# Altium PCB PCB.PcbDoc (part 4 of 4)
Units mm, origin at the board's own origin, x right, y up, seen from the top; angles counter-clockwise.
Board outline 114 x 86.5 mm, 4 copper layers (TOP, GND, SIG, BOTTOM), stack 1.586 mm thick; 98 components, 195 nets, 719 pads, 522 vias.
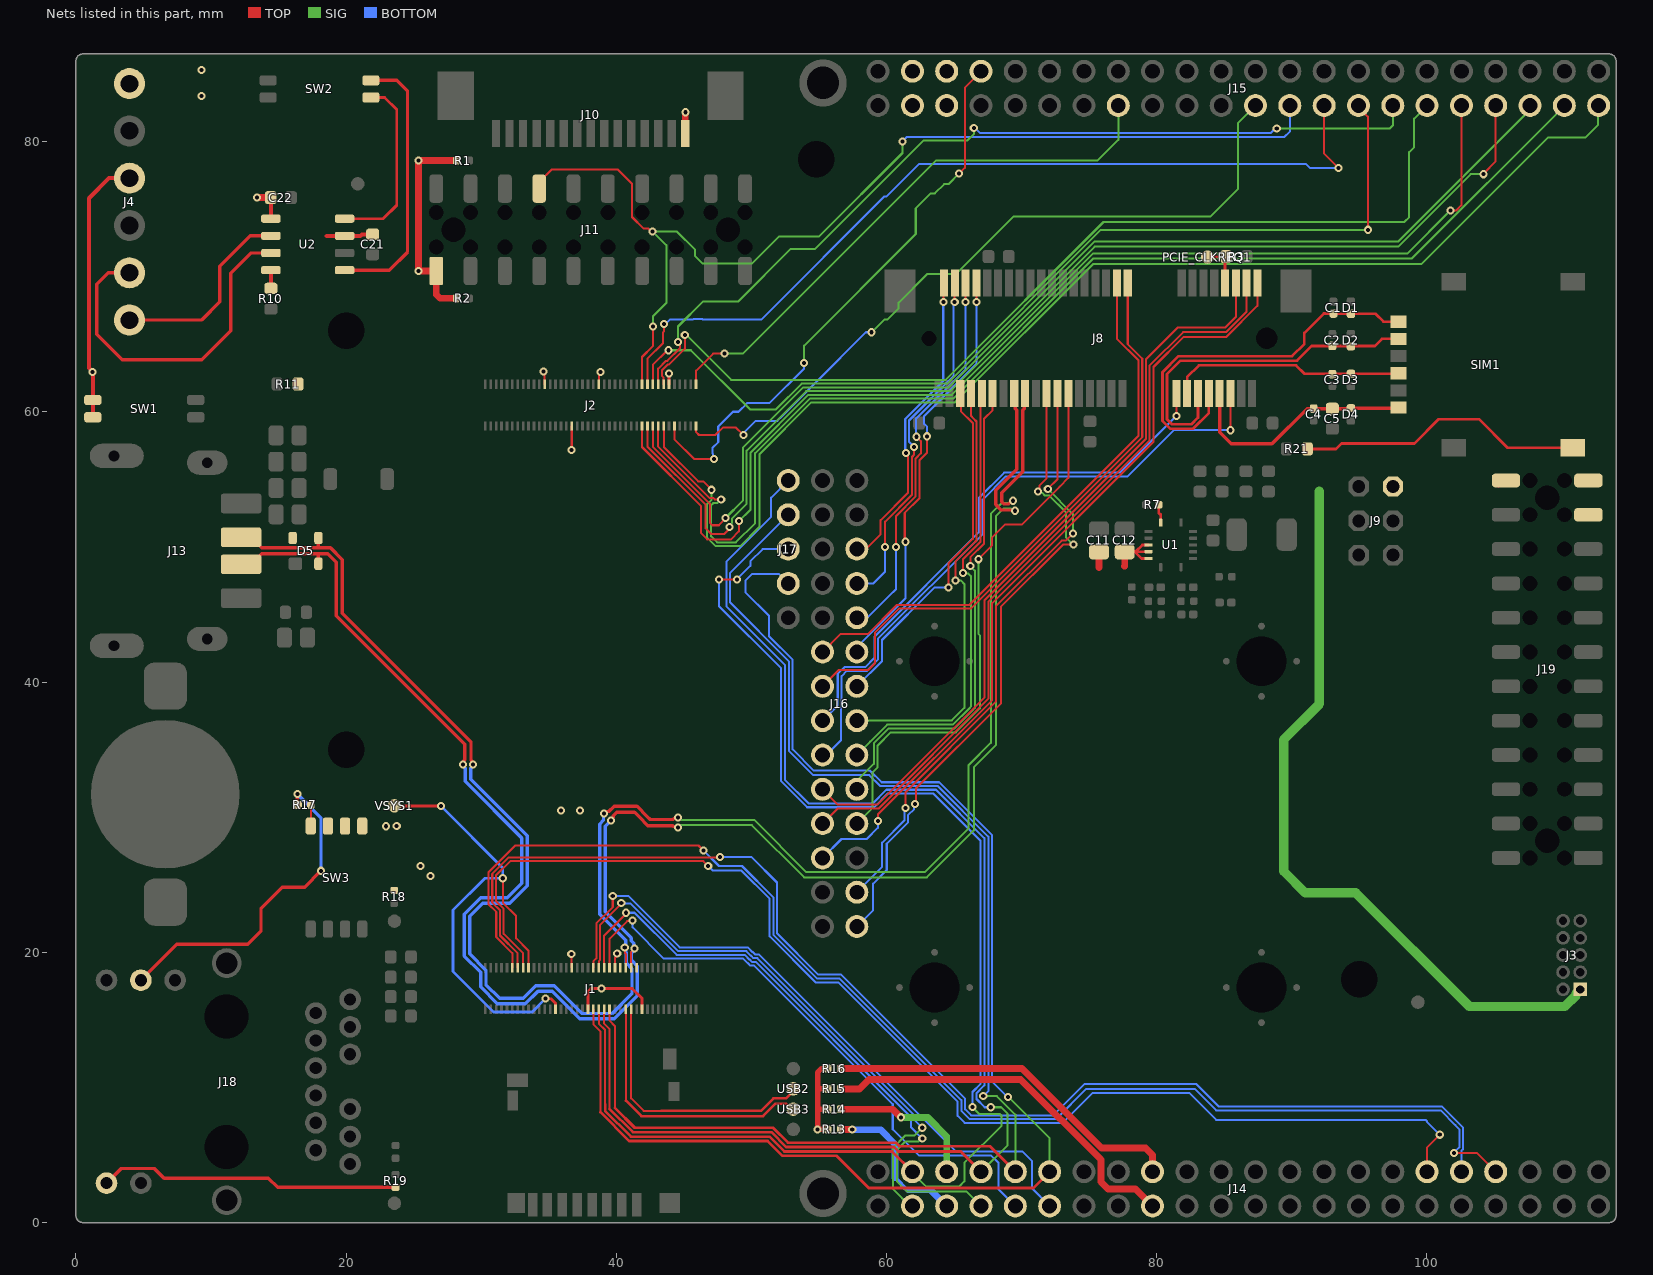
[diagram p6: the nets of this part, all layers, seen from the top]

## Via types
v1: diameter 0.6, hole 0.3, TOP to BOTTOM, tented both sides, 522 vias

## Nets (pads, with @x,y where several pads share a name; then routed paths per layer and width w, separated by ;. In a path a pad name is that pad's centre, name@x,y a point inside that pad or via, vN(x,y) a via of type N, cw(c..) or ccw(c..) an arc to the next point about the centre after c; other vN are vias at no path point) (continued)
NetJ2_79: J2.79 J15.15 | length 41.9
  TOP w0.15: J2.79@45.9,62.04 45.9,63.054 47.169,64.322 47.995,64.322 v1(48.001,64.316)
  SIG w0.15: v1(48.001,64.316) 49.37,64.316 63.672,78.619 75.633,78.619 77.154,80.14 J15.15@77.154,82.68
NetJ2_80: J2.80 J15.23 | length 55.7
  TOP w0.15: J2.80@45.9,58.96 45.9,58.51 46.117,58.293 47.33,58.293 47.881,58.844 48.856,58.844 v1(49.4,58.3)
  SIG w0.15: v1(58.9,65.9) 59.838,66.838 60.038,66.838 60.891,67.691 60.891,68.098 62.995,70.203 65.135,70.203 69.39,74.458 83.961,74.458 86.004,76.5 86.004,78.83 86.004,81.37 J15.23@87.314,82.68
  BOTTOM w0.15: v1(49.4,58.3) 49.4,58.42 50.325,59.345 51.911,59.345 52.261,59.695 54.74,62.174 58.466,65.9 v1(58.9,65.9)
NetJ4_5: J4.5 U2.7 | length 25.9
  TOP w0.25: J4.5@3.962,70.303 2.397,70.303 1.534,69.44 1.534,65.759 3.423,63.87 9.318,63.87 11.456,66.008 11.456,70.272 12.949,71.765 U2.7@14.432,71.765
NetJ4_6: J4.6 U2.6 | length 14.6
  TOP w0.25: J4.6@3.962,66.803 9.293,66.803 10.651,68.161 10.651,70.777 12.909,73.035 U2.6@14.432,73.035
NetJ8_7: J8.7 PCIE_CLKREQ1.X R3.2 | length 3.4
  TOP w0.2: PCIE_CLKREQ1.X@83.759,71.47 83.789,71.5 R3.2@85.125,71.5 85.056,71.431 J8.7@85.056,69.55
NetJ14_5: J14.5 R13.1 | length 11.7
  TOP w0.5: R13.1@56.593,6.892 56.602,6.884 57.454,6.884 v1(57.463,6.876)
  BOTTOM w0.3: 60.629,3.32 61.602,2.347 63.327,2.347
  BOTTOM w0.5: v1(57.463,6.876) 59.548,6.876 60.629,5.794 60.629,3.32 ; 63.327,2.347 J14.5@64.454,1.22
NetJ14_6: J14.6 R14.2 | length 11.3
  TOP w0.5: R14.2@56.593,8.392 60.454,8.392 v1(61.057,7.789)
  SIG w0.5: v1@61.081,7.765 61.086,7.77 61.147,7.77 61.152,7.765 63.074,7.765 64.454,6.385 J14.6@64.454,3.76
NetJ14_17: J14.17 R15.1 | length 28.2
  TOP w0.5: R15.1@56.593,9.892 57.993,9.892 58.693,10.592 69.932,10.592 75.874,4.651 75.874,3.014 76.403,2.485 78.429,2.485 J14.17@79.694,1.22
NetJ14_18: J14.18 R16.2 | length 27
  TOP w0.5: R16.2@56.593,11.392 70.035,11.392 75.918,5.51 79.181,5.51 79.694,4.997 J14.18@79.694,3.76
NetJ18_14: J18.14 R19.1 | length 22.4
  TOP w0.25: J18.14@2.262,2.915 3.347,4 5.8,4 6.517,3.283 14.242,3.283 14.921,2.604 R19.1@23.657,2.604
NetJ18_16: J18.16 R17.1 | length 24.9
  TOP w0.25: J18.16@4.802,17.935 7.467,20.6 12.704,20.6 13.7,21.596 13.7,23.256 15.268,24.824 16.924,24.824 v1(18.136,26.036) ; v1(16.39,31.721) 16.39,30.965 R17.1@16.445,30.91
  BOTTOM w0.25: v1(16.39,31.721) 18.136,29.975 v1(18.136,26.036)
NetR7_2: R7.2 U1.1 | length 1.4
  TOP w0.2: R7.2@80.149,53.127 80.148,52.541 80.299,52.39 U1.1@80.299,51.809
NetR10_2: R10.2 U2.8 | length 1.3
  TOP w0.3: R10.2@14.43,69.156 14.43,70.493 U2.8@14.432,70.495
NetR21_2: R21.2 SIM1.G3 | length 21.4
  TOP w0.2: R21.2@91.151,57.265 93.276,57.265 93.676,57.665 99.076,57.665 100.876,59.465 103.854,59.465 105.969,57.35 SIM1.G3@110.794,57.35
NetSW2_3: SW2.3 U2.4 | length 13.6
  TOP w0.2: U2.4@19.882,74.305 22.747,74.305 23.745,75.303 23.745,82.382 22.853,83.274 SW2.3@21.837,83.274
NetSW2_4: SW2.4 U2.1 | length 20.2
  TOP w0.25: U2.1@19.882,70.495 23.197,70.495 24.544,71.842 24.544,83.745 23.745,84.544 SW2.4@21.837,84.544
PDM.CK_1: J1.66 J14.34 | length 93.6
  TOP w0.15: J1.66@33.1,18.86 33.1,19.928 31.664,21.364 31.664,23.222 31.091,23.795 31.091,25.693 32.153,26.755 46.445,26.755 v1(46.8,26.4) ; J14.34@100.014,3.76 100.014,5.564 v1(100.95,6.5)
  BOTTOM w0.15: v1(46.8,26.4) 47.139,26.061 49.239,26.061 51.341,23.959 51.341,21.18 54.743,17.778 56.421,17.778 65.261,8.939 65.261,7.899 65.78,7.38 73.052,7.38 75.272,9.6 82.4,9.6 84.4,7.6 99.912,7.6 100,7.512 100,7.45 100.2,7.25 v1(100.95,6.5)
PDM.D0_1: J1.68 J14.36 | length 96.3
  TOP w0.15: J1.68@32.7,18.86 32.7,19.936 31.387,21.249 31.387,23.107 30.814,23.681 30.814,25.807 32.038,27.032 47.666,27.032 v1(47.684,27.049)
  BOTTOM w0.15: v1(47.684,27.049) 50.016,27.049 51.895,25.17 51.895,21.41 54.952,18.353 56.634,18.353 65.815,9.172 65.815,8.386 66.267,7.934 72.334,7.934 74.646,10.246 82.944,10.246 84.613,8.577 101.127,8.577 102.687,7.018 102.687,5.445 102.554,5.312 J14.36@102.554,3.76
PDM.D1_1: J1.70 J14.38 | length 98.7
  TOP w0.15: J1.70@32.3,18.86 32.3,19.944 31.11,21.134 31.11,22.992 30.537,23.566 30.537,25.922 32.522,27.907 46.083,27.907 v1(46.457,27.534) ; v1(102,5.15) 103.704,5.15 J14.38@105.094,3.76
  BOTTOM w0.15: v1(46.457,27.534) 47.6,26.39 49.301,26.39 51.618,24.074 51.618,21.295 54.858,18.055 56.536,18.055 65.538,9.053 65.538,8.271 66.152,7.657 72.547,7.657 74.79,9.9 82.8,9.9 84.4,8.3 101.013,8.3 102.108,7.204 102.41,6.903 102.41,5.56 v1(102,5.15)
PIN1_3: J8.1 J16.23 | length 58.8
  TOP w0.15: v1(59.357,29.732) 59.357,30.202 67.821,38.666 67.821,45.851 79.76,57.79 79.76,63.33 81.99,65.56 85.168,65.56 87.456,67.847 J8.1@87.456,69.55
  BOTTOM w0.15: J16.23@55.264,26.989 56.667,28.392 58.53,28.392 59.357,29.22 v1(59.357,29.732)
PIN3_3: J8.3 J16.21 | length 56.7
  TOP w0.15: J16.21@55.264,29.529 56.384,30.649 59.413,30.649 67.544,38.781 67.544,45.965 79.483,57.904 79.483,63.444 81.952,65.913 85.13,65.913 86.656,67.439 J8.3@86.656,69.55
PIN5_3: J8.5 J16.19 | length 56.2
  TOP w0.15: J16.19@55.264,32.069 56.4,30.933 59.305,30.933 67.267,38.896 67.267,46.08 79.206,58.019 79.206,63.906 81.549,66.249 85.074,66.249 85.856,67.031 J8.5@85.856,69.55
PIN6_3: J8.6 J16.17 | length 48
  TOP w0.15: v1@85.456,58.648 J8.6@85.456,61.35
  BOTTOM w0.15: J16.17@55.264,34.609 55.55,34.609 56.623,35.682 56.623,38.117 56.68,38.173 56.68,40.448 57.069,40.837 58.539,40.837 59.386,41.684 59.386,43.236 67.11,50.96 67.11,53.517 68.828,55.235 77.85,55.235 81.268,58.654 85.451,58.654 v1(85.458,58.647)
PIN16_3: J8.16 J16.15 | length 41
  TOP w0.15: v1(81.45,59.7) 81.45,61.344 J8.16@81.456,61.35
  BOTTOM w0.15: J16.15@55.264,37.149 56.389,38.274 56.389,40.616 56.887,41.114 58.424,41.114 59.109,41.799 59.109,43.357 66.833,51.081 66.833,53.632 68.713,55.512 77.262,55.512 v1(81.45,59.7)
PIN17_3: J8.17 J16.13 | length 44.5
  TOP w0.15: J16.13@55.264,39.689 56.476,40.901 58.66,40.901 59.141,41.383 59.141,43.658 60.919,45.436 65.417,45.436 66.231,45.436 78.929,58.134 78.929,58.877 78.929,63.951 77.856,65.024 J8.17@77.856,69.55
PIN19_3: J8.19 J16.11 | length 42
  TOP w0.15: J16.11@55.264,42.229 56.584,43.549 58.598,43.549 60.761,45.713 66.117,45.713 78.652,58.248 78.652,63.836 77.056,65.433 J8.19@77.056,69.55
PIN28_3: J8.28 J16.22 | length 41.9
  TOP w0.15: v1(66.8,49.1) 67.824,50.124 67.824,50.72 68.763,51.658 69.999,51.658 72.817,54.477 73.456,55.115 J8.28@73.456,61.35
  SIG w0.15: J16.22@57.804,29.529 58.945,30.671 58.945,33.294 59.342,33.69 59.342,35.31 60.322,36.29 65.139,36.29 66.91,38.061 66.91,43.464 66.823,43.551 66.823,49.077 v1(66.8,49.1)
PIN30_3: J8.30 J16.26 | length 44.8
  TOP w0.15: v1(61.403,30.687) 61.403,31.857 68.098,38.552 68.098,45.609 72.958,50.469 73.275,50.469 v1(73.798,50.992) ; v1(71.936,54.306) 72.656,55.025 J8.30@72.656,61.35
  SIG w0.15: v1(71.936,54.306) 73.798,52.444 v1(73.798,50.992)
  BOTTOM w0.15: J16.26@57.804,24.449 59.678,26.323 59.678,28.111 61.33,29.764 61.33,30.614 v1(61.403,30.687)
PIN32_3: J8.32 J16.28 | length 48.2
  TOP w0.15: v1(62.098,30.992) 62.184,31.078 62.184,32.136 68.464,38.415 68.464,45.583 73.073,50.192 v1(73.837,50.192) ; v1(71.205,54.099) 71.205,54.22 71.338,54.352 71.338,54.563 71.856,55.081 J8.32@71.856,61.35
  SIG w0.15: v1(71.205,54.099) 71.292,54.012 71.52,54.012 71.729,53.804 72.047,53.804 73.291,52.559 73.291,50.7 73.799,50.192 v1(73.837,50.192)
  BOTTOM w0.15: J16.28@57.804,21.909 59.013,23.118 59.013,25.089 60.016,26.092 60.016,28.046 61.607,29.637 61.607,30.173 62.041,30.607 62.041,30.935 v1(62.098,30.992)
PIN42_3: J8.42 J16.20 | length 36.6
  TOP w0.15: v1(66.2,48.6) 66.2,49.243 67.216,50.259 67.216,59.493 67.856,60.133 J8.42@67.856,61.35
  SIG w0.15: J16.20@57.804,32.069 57.804,32.689 59.064,33.949 59.064,35.485 60.162,36.583 65.032,36.583 66.38,37.931 66.546,38.097 66.546,48.254 v1(66.2,48.6)
PIN44_3: J8.44 J16.18 | length 34.1
  TOP w0.15: v1(65.663,48.071) 65.663,49.098 66.939,50.374 66.939,61.233 J8.44@67.056,61.35
  SIG w0.15: J16.18@57.804,34.609 58.787,35.592 58.787,35.6 60.047,36.86 60.055,36.86 60.072,36.877 64.934,36.877 66.103,38.046 66.269,38.212 66.269,47.82 66.063,48.026 65.708,48.026 v1(65.663,48.071)
PIN45_3: J8.45 J16.12 | length 31.2
  TOP w0.15: v1(61.398,50.392) 61.348,50.443 61.348,52.529 62.438,53.619 62.438,56.438 63,57 v1(63,58.2) ; J8.45@66.656,69.55 66.659,69.546 v1(66.659,68.14)
  BOTTOM w0.15: J16.12@57.804,42.229 57.804,42.598 61.398,46.192 v1(61.398,50.392) ; v1(63,58.2) 63,58.901 62.779,59.121 62.779,59.7 66.659,63.58 v1(66.659,68.14)
PIN46_3: J8.46 J16.16 | length 32.9
  TOP w0.15: v1(65.1,47.538) 65.1,48.926 66.431,50.257 66.662,50.488 66.662,59.297 66.431,59.529 66.256,59.703 J8.46@66.256,61.35
  SIG w0.15: J16.16@57.804,37.149 57.819,37.164 64.83,37.164 65.766,38.101 65.766,47.265 65.5,47.532 65.106,47.532 v1(65.1,47.538)
PIN47_3: J8.47 J16.10 | length 28.9
  TOP w0.15: v1(60.698,49.992) 60.698,52.284 62.161,53.747 62.161,56.553 62.537,56.929 62.537,57.841 v1(62.21,58.167) ; v1(65.857,68.153) J8.47@65.856,69.55
  BOTTOM w0.15: J16.10@57.804,44.769 58.584,44.769 60.2,46.386 60.698,46.884 v1(60.698,49.992) ; v1(62.21,58.167) 62.165,58.213 62.165,59.477 65.857,63.169 v1(65.857,68.153)
PIN48_3: J8.48 J16.14 | length 26.2
  TOP w0.15: v1(64.6,47) 64.6,47.328 64.598,47.33 64.598,47.746 64.6,47.748 64.6,48.818 66.385,50.603 66.385,59.182 65.5,60.068 65.5,61.306 J8.48@65.456,61.35
  BOTTOM w0.15: J16.14@57.804,39.689 59.663,41.548 59.663,43.121 63.542,47 v1(64.6,47)
PIN49_3: J8.49 J16.8 | length 26.3
  TOP w0.15: v1(59.898,49.992) 59.898,51.876 61.884,53.861 61.884,56.668 62.035,56.818 v1(62.035,57.411) ; v1(65.048,68.14) 65.048,69.542 J8.49@65.056,69.55
  BOTTOM w0.15: J16.8@57.804,47.309 59.035,47.309 59.887,48.161 59.887,49.981 v1(59.898,49.992) ; v1(62.035,57.411) 61.663,57.783 61.663,59.367 64.963,62.667 64.963,68.055 v1(65.048,68.14)
PIN51_3: J8.51 J16.6 | length 22.9
  TOP w0.15: J16.6@57.804,49.849 58.464,49.849 59.564,50.949 59.564,51.988 61.587,54.011 61.587,56.71 61.446,56.85 v1(61.446,56.972) ; v1(64.226,68.128) 64.226,69.52 J8.51@64.256,69.55
  BOTTOM w0.15: v1(61.446,56.972) 61.386,57.033 61.386,59.482 64.198,62.294 64.198,68.1 v1(64.226,68.128)
PWM0_1: J2.59 J11.8 J15.25 | length 80
  TOP w0.15: J11.8@34.29,76.535 34.29,77.031 35.204,77.945 40.096,77.945 41.158,76.883 41.158,74.433 42.028,73.563 42.374,73.563 42.584,73.354 v1(42.687,73.354) ; J2.59@41.9,62.04 41.9,64.068 42.7,64.868 42.7,66.327 v1(42.702,66.329)
  SIG w0.15: v1(42.702,66.329) 42.702,67.066 43.704,68.068 43.704,69.96 43.698,69.966 43.698,72.343 v1(42.687,73.354) 44.491,73.354 45.839,72.006 45.839,71.528 46.367,71 50.049,71 52.05,73.001 55.017,73.001 61.185,79.168 v1(61.185,80.033)
  BOTTOM w0.15: v1(61.185,80.033) 61.513,80.362 89.459,80.362 89.854,80.757 J15.25@89.854,82.68
PWM5: J2.60 J15.35 | length 86.8
  TOP w0.15: J2.60@41.9,58.96 41.9,57.405 46.271,53.034 46.271,51.023 46.719,50.575 48.496,50.575 49.076,51.156 v1(49.076,51.916) ; v1(101.735,74.916) 102.165,74.916 102.548,75.299 102.548,82.674 J15.35@102.554,82.68
  SIG w0.15: v1(49.076,51.916) 49.93,52.77 49.93,56.99 54.207,61.267 64.83,61.267 75.277,71.714 98.534,71.714 v1(101.735,74.916)
PWM6: J2.62 J15.37 | length 86.2
  TOP w0.15: J2.62@42.3,58.96 42.3,57.446 46.616,53.13 46.616,51.383 47.032,50.967 47.975,50.967 48.375,51.368 v1(48.375,51.473) ; v1(104.2,77.6) 104.2,77.651 105.094,78.545 J15.37@105.094,82.68
  SIG w0.15: v1(48.375,51.473) 48.375,51.594 48.574,51.793 48.574,52.124 49.646,53.196 49.646,57.136 54.054,61.544 64.715,61.544 75.405,72.234 97.874,72.234 103.241,77.6 v1(104.2,77.6)
PWM7: J2.64 J15.39 | length 85.1
  TOP w0.15: J2.64@42.7,58.96 42.7,57.438 46.926,53.212 46.926,51.789 47.102,51.614 47.592,51.614 48.073,52.095 v1(48.073,52.15)
  SIG w0.15: v1(48.073,52.15) 48.08,52.15 49.364,53.433 49.364,57.345 53.84,61.821 64.6,61.821 75.391,72.612 97.861,72.612 107.634,82.385 J15.39@107.634,82.68
PWM8: J2.66 J15.41 | length 90.8
  TOP w0.15: J2.66@43.1,58.96 43.1,57.429 46.892,53.637 47.162,53.637 47.274,53.526 v1(47.762,53.526)
  SIG w0.15: v1(47.762,53.526) 47.729,53.526 47.463,53.26 47.191,53.26 47.015,53.084 47.015,50.791 47.458,50.348 47.879,50.348 48.29,50.348 48.852,50.348 50.278,51.774 50.278,56.946 54.322,60.99 64.945,60.99 75.311,71.357 76.037,71.357 98.486,71.357 98.887,71.357 110.174,82.645 J15.41@110.174,82.68
PWM9: J2.68 J15.43 | length 93.8
  TOP w0.15: J2.68@43.5,58.96 43.512,58.948 43.512,57.409 46.051,54.87 46.397,54.87 46.425,54.87 v1(47.056,54.239)
  SIG w0.15: v1(47.056,54.239) 47.056,53.517 46.724,53.185 46.724,50.691 47.343,50.071 48.405,50.071 49.181,50.071 50.598,51.488 50.598,56.875 54.437,60.713 65.059,60.713 75.283,70.937 99.287,70.937 99.586,70.937 108.95,80.301 111.718,80.301 112.65,81.233 112.65,82.616 J15.43@112.714,82.68
PWM.1_1: J2.61 J15.27 | length 65.1
  TOP w0.15: J2.61@42.3,62.04 42.3,63.945 43.452,65.097 43.452,65.887 43.544,65.978 43.544,66.487 v1(43.519,66.512) ; J15.27@92.394,82.68 92.394,79.115 v1(93.464,78.045)
  BOTTOM w0.15: v1(43.519,66.512) 43.634,66.512 43.977,66.855 45.682,66.855 45.719,66.892 46.356,66.892 46.393,66.855 50.75,66.855 59.85,75.955 60.008,75.955 62.394,78.342 91.059,78.342 91.356,78.045 v1(93.464,78.045)
PWM.2_1: J2.63 J15.29 | length 71.6
  TOP w0.15: J2.63@42.7,62.04 42.7,63.48 43.79,64.569 v1(43.853,64.569) ; J15.29@94.934,82.68 94.934,82.565 95.635,81.865 v1(95.635,73.485)
  SIG w0.15: v1(43.853,64.569) 43.854,64.568 45.519,64.568 49.904,60.183 51.81,60.183 53.725,62.098 64.486,62.098 75.872,73.485 v1(95.635,73.485)
PWM.3_1: J2.65 J15.31 | length 66.2
  TOP w0.15: J2.65@43.1,62.04 43.1,63.211 43.675,63.785 43.78,63.785 44.728,64.733 44.728,64.885 44.564,65.048 v1(44.564,65.17)
  SIG w0.15: v1(44.564,65.17) 44.564,66.324 46.433,68.194 49.043,68.194 52.923,72.074 54.717,72.074 62.744,80.101 65.995,80.101 66.459,80.565 v1(66.459,81.013) ; v1(88.885,80.981) 97.248,80.981 97.474,81.206 J15.31@97.474,82.68
  BOTTOM w0.15: v1(66.459,81.013) 66.558,81.013 66.933,80.639 88.422,80.639 88.764,80.981 v1(88.885,80.981)
PWM.4_1: J2.67 J15.33 | length 73.3
  TOP w0.15: J2.67@43.5,62.04 43.5,62.533 43.386,62.647 43.386,63.104 43.79,63.508 43.895,63.508 45.066,64.68 v1(45.066,65.707)
  SIG w0.15: v1(45.066,65.707) 45.163,65.707 48.495,62.375 64.371,62.375 76.058,74.062 98.326,74.062 98.684,74.421 98.684,79.235 99.05,79.601 99.05,81.716 J15.33@100.014,82.68
SERIAL0.CTS_1: J1.40 J14.11 | length 49
  TOP w0.15: J1.40@38.3,18.86 38.3,19.325 38.527,19.552 38.527,22.144 39.735,23.352 v1(39.735,24.18)
  BOTTOM w0.15: v1(39.735,24.18) 40.878,24.18 44.695,20.363 49.737,20.363 50.075,20.024 50.09,20.024 50.263,19.851 50.545,19.851 65.149,5.247 70.074,5.247 70.774,4.547 70.774,2.52 J14.11@72.074,1.22
SERIAL0.RTS_1: J1.38 J14.3 | length 42.6
  TOP w0.15: J1.38@38.7,18.86 38.7,19.333 38.804,19.437 38.804,22.029 40.365,23.59 v1(40.365,23.659)
  SIG w0.15: J14.3@61.914,1.22 61.74,1.22 60.482,2.478 60.482,5.542 61.368,6.427 62.052,6.427 v1(62.643,7.017)
  BOTTOM w0.15: v1(40.365,23.659) 40.423,23.602 41.064,23.602 44.58,20.086 49.622,20.086 49.96,19.747 49.975,19.747 50.148,19.574 50.43,19.574 62.091,7.914 62.091,7.569 v1(62.643,7.017)
SERIAL0.RX_1: J1.36 J14.7 | length 45.6
  TOP w0.15: J1.36@39.1,18.86 39.1,19.989 39.099,19.99 39.099,21.247 40.727,22.875 v1(40.727,22.931)
  SIG w0.15: v1(62.647,6.206) 62.543,6.206 62.334,5.997 61.39,5.997 60.763,5.371 60.763,3.053 61.511,2.305 65.909,2.305 J14.7@66.994,1.22
  BOTTOM w0.15: v1(40.727,22.931) 41.343,22.931 44.465,19.809 49.507,19.809 49.846,19.47 49.86,19.47 50.033,19.297 50.316,19.297 61.814,7.799 61.814,7.04 v1(62.647,6.206)
SERIAL0.TX_1: J1.34 J14.9 | length 44
  TOP w0.15: J1.34@39.509,18.869 39.509,21.011 40.803,22.305 41.155,22.305 v1(41.2,22.35)
  BOTTOM w0.15: v1(41.2,22.35) 41.2,21.843 43.512,19.532 49.392,19.532 49.731,19.193 49.745,19.193 49.919,19.02 50.201,19.02 60.46,8.761 60.46,6.9 62.39,4.97 67.729,4.97 68.288,4.41 68.288,2.466 J14.9@69.534,1.22
SERIAL1.CTS_1: J1.39 J14.12 J17.4 | length 105.6
  TOP w0.15: J1.39@38.3,15.78 38.3,14.669 38.813,14.155 38.813,8.167
  TOP w0.2: 38.813,8.167 40.947,6.033 51.2,6.033 52.3,4.933 56.315,4.933 58.686,2.562 70.876,2.562 J14.12@72.074,3.76
  SIG w0.15: v1(69,9.3) 72.074,6.226 J14.12@72.074,3.76
  BOTTOM w0.15: J17.4@52.724,47.309 52.021,48.012 50.049,48.012 49.553,47.517 49.553,46.647 51.3,44.9 51.3,43.405 53.054,41.651 53.054,35.024 54.624,33.455 58.779,33.455 59.644,32.59 63.894,32.59 67.813,28.671 67.813,10.411 68.923,9.3 v1(69,9.3)
SERIAL1.RTS_1: J1.37 J14.4 J17.3 | length 105.7
  TOP w0.15: J1.37@38.7,15.78 38.7,14.726 39.173,14.253 39.173,8.732 ; v1(47.598,47.592) 47.606,47.599 48.915,47.599 v1(48.922,47.607)
  TOP w0.2: 39.173,8.732 39.173,8.27 41.083,6.36 51.336,6.36 52.436,5.26 60.414,5.26 J14.4@61.914,3.76
  SIG w0.15: J14.4@61.914,3.76 61.914,3.663 62.926,2.651 65.365,2.651 65.764,3.049 65.764,4.417 68.517,7.17 68.517,7.893 68.377,8.032 66.879,8.032 v1(66.366,8.545)
  BOTTOM w0.15: v1(47.598,47.592) 47.598,45.615 52.195,41.019 52.195,32.668 54.123,30.74 59.085,30.74 60.103,31.759 63.455,31.759 66.971,28.243 66.971,10.265 66.366,9.66 v1(66.366,8.545) ; v1(48.922,47.607) 49.918,48.603 49.918,48.939 50.828,49.849 J17.3@52.724,49.849
SERIAL1.RX_1: J1.35 J14.8 J17.1 | length 107.6
  TOP w0.15: J1.35@39.1,15.78 39.1,14.718 39.5,14.318 39.5,8.405
  TOP w0.2: 39.5,8.405 41.218,6.687 51.471,6.687 52.571,5.587 60.55,5.587 60.877,5.26 65.494,5.26 J14.8@66.994,3.76
  SIG w0.15: J14.8@66.994,3.76 68.964,5.73 68.964,8.049 68.479,8.534 v1(67.715,8.534)
  BOTTOM w0.15: J17.1@52.724,54.929 51.452,53.657 51.452,52.237 48.142,48.927 48.142,45.616 52.472,41.286 52.472,32.783 54.237,31.017 58.97,31.017 59.988,32.036 63.665,32.036 67.248,28.453 67.248,10.15 66.658,9.561 66.658,9.145 67.269,8.534 v1(67.715,8.534)
SERIAL1.TX_1: J1.33 J14.10 J17.2 | length 104
  TOP w0.15: J1.33@39.5,15.78 39.5,14.944 39.9,14.544 39.9,8.479
  TOP w0.2: 39.9,8.479 41.365,7.014 51.606,7.014 52.707,5.914 60.685,5.914 60.952,5.647 67.647,5.647 J14.10@69.534,3.76
  SIG w0.15: v1(67.16,9.353) 68.161,9.353 69.534,7.979 J14.10@69.534,3.76
  BOTTOM w0.15: J17.2@52.724,52.389 48.419,48.084 48.419,45.895 52.777,41.536 52.777,34.91 54.566,33.121 58.72,33.121 59.529,32.313 63.779,32.313 67.536,28.556 67.536,9.728 v1(67.16,9.353)
USB0_D_N: D5.3 J1.28 J8.36 J13.2 | length 145.2
  TOP w0.15: v1(40.624,20.373) 40.624,19.951 40.725,19.85 40.725,19.435 40.725,19.185 40.725,18.885 J1.28@40.7,18.86
  TOP w0.25: J13.2@12.222,50.723 12.97,50.723 13.743,49.949 15.722,49.949 17.852,49.949 ; D5.3@17.943,50.677 17.943,50.04 17.852,49.949 ; v1(29.377,33.9) 29.31,33.967 29.31,34.195 29.238,34.266 29.238,35.587 19.714,45.112 19.714,49.076 18.841,49.949 17.852,49.949 ; v1(39.086,30.264) 39.181,30.264 39.342,30.425 39.443,30.425 39.836,30.818 41.533,30.818 42.305,30.046 42.518,29.834 44.184,29.834 44.255,29.905 44.483,29.905 v1(44.55,29.972) ; v1(69.363,53.426) 69.278,53.426 69.041,53.189 68.688,53.189 68.542,53.336 68.542,54.029 70.081,55.568 70.081,58.678 70.081,60.144 70.186,60.25 70.186,61.28 J8.36@70.256,61.35
  SIG w0.15: v1(44.55,29.972) 44.672,29.972 44.84,29.804 50.196,29.804 54.063,25.937 62.827,25.937 66.074,29.184 66.074,33.868 67.721,35.515 67.721,52.465 68.509,53.253 69.068,53.253 69.242,53.426 v1(69.363,53.426)
  BOTTOM w0.25: v1(29.377,33.9) 29.377,33.805 29.214,33.642 29.214,32.815 33.4,28.628 33.4,24.934 32.098,23.632 30.119,23.632 29.148,22.661 29.148,19.893 30.351,18.69 30.351,17.607 31.363,16.595 33.108,16.595 34.034,17.521 35.417,17.521 37.468,15.471 39.68,15.471 41.156,16.947 41.156,18.804 40.724,19.236 40.724,19.958 40.691,19.991 40.691,20.306 v1(40.624,20.373) 40.691,20.44 40.691,20.687 40.696,20.692 40.696,20.899 38.771,22.825 38.771,29.486 39.048,29.764 39.048,30.226 v1(39.086,30.264)
USB0_D_P: D5.2 J1.26 J8.38 J13.3 | length 145.9
  TOP w0.15: J1.26@41.1,18.86 41.075,18.885 41.075,19.58 41.075,19.996 41.346,20.267 v1(41.346,20.291)
  TOP w0.25: J13.3@12.222,48.723 12.968,48.723 13.745,49.499 15.909,49.499 18.654,49.499 19.264,48.889 19.264,44.925 28.788,35.401 28.788,34.266 28.717,34.195 28.717,33.967 v1(28.65,33.9) ; D5.2@17.943,48.767 17.943,49.405 ; v1(39.6,29.75) 39.6,29.845 39.761,30.006 39.761,30.107 40.022,30.368 41.347,30.368 41.683,30.031 42.331,29.384 44.184,29.384 44.255,29.312 44.483,29.312 v1(44.55,29.245) ; J8.38@69.456,61.35 69.526,61.28 69.526,60.25 69.631,60.144 69.631,58.678 69.631,57.484 69.631,55.755 68.092,54.216 68.092,53.149 68.502,52.739 69.446,52.739 v1(69.496,52.689)
  SIG w0.15: v1(44.55,29.245) 44.672,29.245 44.84,29.414 50.035,29.414 53.901,25.547 62.989,25.547 66.464,29.023 66.464,33.706 68.111,35.354 68.111,52.304 68.67,52.863 69.201,52.863 69.374,52.689 v1(69.496,52.689)
  BOTTOM w0.25: v1@28.65,33.954 v1(28.65,33.9) 28.65,33.805 28.814,33.642 28.814,32.649 33,28.463 33,25.1 31.932,24.032 29.954,24.032 28.748,22.827 28.748,19.727 29.951,18.524 29.951,17.442 31.198,16.195 33.274,16.195 34.2,17.121 35.251,17.121 37.302,15.071 39.845,15.071 41.556,16.782 41.556,18.969 41.124,19.402 41.124,19.974 41.346,20.196 v1(41.346,20.291) 41.279,20.358 41.279,20.672 41.096,20.855 41.096,21.065 39.171,22.99 39.171,29.321 v1(39.6,29.75)
USB0_HOST.ID_1: J1.30
USB0_HOST.VBUS_1: J1.24
USB1_D_N: J1.27 USB3.X | length 20.2
  TOP w0.15: 40.7,9.019 J1.27@40.7,15.78
  TOP w0.2: 40.7,9.019 41.849,7.87 50.858,7.87 51.783,8.796 52.573,8.796 USB3.X@53.098,8.27
USB1_D_P: J1.25 USB2.X | length 19.6
  TOP w0.15: J1.25@41.1,15.78 41.1,9.185 42.015,8.27 43.331,8.27
  TOP w0.2: 43.331,8.27 50.692,8.27 51.617,9.196 52.573,9.196 USB2.X@53.098,9.721
USIM_CLK_3: C2.2 D2.C J8.12 SIM1.C3 | length 26.4
  TOP w0.2: J8.12@83.056,61.35 83.056,59.577 82.569,59.091 81.127,59.091 80.757,59.461 80.757,62.803 81.754,63.801 90.38,63.801 91.465,64.886 C2.2@93,64.886 96.144,64.886 96.668,65.41 SIM1.C3@97.894,65.41 SIM1.C3@97.606,65.122
USIM_DATA_3: C1.2 D1.C J8.10 SIM1.C7 | length 29.2
  TOP w0.2: J8.10@83.856,61.35 83.856,59.915 82.705,58.764 80.992,58.764 80.43,59.326 80.43,62.939 81.619,64.128 90.026,64.128 90.931,65.033 90.931,65.845 92.372,67.286 C1.2@93.083,67.286 93.098,67.271 D1.C@94.376,67.271 96.198,67.271 96.789,66.68 SIM1.C7@97.894,66.68
USIM_PWR_3: C4.2 C5.2 D4.C J8.8 SIM1.C1 | length 17.6
  TOP w0.25: J8.8@84.656,61.35 84.656,58.497 85.512,57.642 88.534,57.642 91.142,60.25 C4.2@91.622,60.25 ; C4.2@91.622,60.228 93,60.228 D4.C@94.376,60.228 ; D4.C@94.376,60.265 97.829,60.265 SIM1.C1@97.894,60.33
USIM_RST_3: C3.2 D3.C J8.14 SIM1.C2 | length 17.5
  TOP w0.2: J8.14@82.256,61.35 82.256,62.577 83.131,63.452 90.307,63.452 90.931,62.828 D3.C@94.376,62.828 ; D3.C@94.376,62.818 97.842,62.818 SIM1.C2@97.894,62.87
VCC: C22.1 J2.23 J2.34 J2.43 J2.69 J3.1 J4.3 J9.2 J10.15 J11.1 J15.3 J15.4 J19.23 R1.2 R2.2 R17.2 R18.2 SW1.3 SW1.4 SW3.5 SW3.6 SW3.7 SW3.8 U2.5 | length 101.8
  TOP w0.15: SW3.8@17.379,29.346 17.395,29.362 R17.2@17.395,30.91 ; v1(34.62,62.984) 34.675,62.929 34.675,62.065 J2.23@34.7,62.04 ; v1(36.676,57.172) 36.7,57.197 J2.34@36.7,58.96 ; J2.43@38.7,62.04 38.7,62.714 38.823,62.837 v1(38.823,62.959)
  TOP w0.2: v1(43.89,62.853) 43.9,62.843 J2.69@43.9,62.04
  TOP w0.3: SW1.4@1.245,59.612 SW1.3@1.245,60.882 1.245,62.934 v1(1.228,62.951) 1.228,63 0.97,63.258 0.97,75.82 2.454,77.303 J4.3@3.962,77.303 ; C22.1@14.417,75.866 14.432,75.851 U2.5@14.432,74.305
  TOP w0.5: v1(13.395,75.867) C22.1@14.417,75.866 ; U2.5@14.417,74.32 U2.5@14.432,74.305 ; R1.2@28.112,78.612 v1(25.35,78.612) v1(25.35,70.435) J11.1@26.67,70.435 26.67,68.704 26.963,68.411 R2.2@28.167,68.411 ; J10.15@45.1,80.6 45.1,82.181 v1(45.105,82.186)
  SIG w0.7: 92.044,54.116 92.044,38.394 89.4,35.75 89.4,26 90.999,24.401 94.736,24.401 103.147,15.99 110.202,15.99 111.064,16.852 111.064,16.975 J3.1@111.349,17.26
  other v1: 22.962,29.333 23.742,29.346
VIN: C11.2 C12.2 C21.1 D5.4 J1.21 J1.32 J1.41 J1.48 J4.1 J15.5 J15.6 J19.21 J19.24 R11.1 R13.2 R14.1 R15.2 R16.1 U1.4 U1.5 U1.6 U2.3 | length 27.4
  TOP w0.15: v1(36.665,19.883) 36.682,19.866 36.682,18.878 J1.48@36.7,18.86 ; J1.32@39.9,18.867 39.9,19.621 40.065,19.786 v1(40.065,19.907)
  TOP w0.2: J1.41@37.9,15.78 37.9,17.115 38.115,17.33 v1(38.916,17.33) 41.17,17.33 41.9,16.6 J1.21@41.9,15.78 ; C12.2@77.627,49.641 C12.2@78.019,49.641 ; C12.2@78.019,49.671 78.448,49.671 78.936,50.159 U1.4@79.399,50.159 ; C12.2@78.362,49.671 78.874,49.159 U1.6@79.399,49.159 ; 78.448,49.659 U1.5@79.399,49.659 ; C12.2@77.645,49.659 77.832,49.846 78.019,49.659 C12.2@77.645,49.659
  TOP w0.3: 18.562,73.035 U2.3@19.882,73.035 21.042,73.035 21.157,73.15 C21.1@21.964,73.15
  TOP w0.4: R13.2@55.643,6.892 v1(54.898,6.892) 54.898,8.392 ; R14.1@55.643,8.392 54.898,8.392 ; R15.2@55.643,9.892 54.898,9.892 ; R16.1@55.643,11.392 55.198,11.392 54.898,11.092 54.898,9.892 ; 54.898,8.392 54.898,9.892
  TOP w0.5: 75.724,48.488 C11.2@75.724,49.641 ; 77.622,48.576 77.627,48.582 C12.2@77.627,49.641 ; J19.24@105.309,54.67 105.569,54.929 J19.24@105.854,54.929
  other v1: 26.25,25.65 25.5,26.4 35.9,30.5 37.3,30.5 9.3,83.4 9.3,85.3
VREF_N: J2.72 J15.8 | length 43.1
  TOP w0.15: J2.72@44.3,58.96 44.3,57.995 45.787,56.508 v1(47.238,56.508) ; v1(65.368,77.639) 65.8,78.072 65.8,84 66.994,85.194 J15.8@66.994,85.22
  SIG w0.15: v1(53.898,63.619) 53.898,64.911 62.163,73.175 62.163,75.076 63.262,76.176 63.58,76.176 64.268,76.864 64.587,76.864 65.361,77.639 v1(65.368,77.639)
  BOTTOM w0.15: v1(47.238,56.508) 47.151,56.595 47.151,56.897 47.118,56.93 47.118,57.346 47.544,57.772 47.544,58.926 48.635,60.016 49.041,60.016 49.676,60.651 51.331,60.651 53.898,63.218 v1(53.898,63.619)
VSYS: J1.53 J1.64 VSYS1.X | length 37.1
  TOP w0.15: v1(31.593,25.485) 31.593,23.685 32.589,22.688 32.589,21.042 33.5,20.132 J1.64@33.5,18.86
  TOP w0.2: VSYS1.X@23.578,30.848 23.587,30.839 27.004,30.839 v1(27.013,30.83) ; v1(34.764,16.569) 34.767,16.566 35.164,16.566 35.5,16.23 J1.53@35.5,15.78
  BOTTOM w0.2: v1(27.013,30.83) 31.593,26.25 v1(31.593,25.485) 30.277,25.485 27.916,23.124 27.916,18.58 30.914,15.582 33.777,15.582 v1(34.764,16.569)
pads on no net: Fiducial_1.1 Fiducial_2.1 H1.0 H2.0 H3.0 H4.0 J3.7 J8.MH1 J8.MH2 J8.MP1 J8.MP2 J9.5 J10.12 J11.0 J13.SHIELD1 J13.SHIELD3 J13.SHIELD4 J18.17 J18.SHNP1 J18.SHNP2 J19.0 J19.19 J19.20 SIM1.C6 U1.14

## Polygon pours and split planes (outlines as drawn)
GND on BOTTOM "GND_L04_P132" (solid, remove dead copper, pour order 132): 114.004,86.502 114.004,0.002 0,0.002 0,86.502
+3V3_PCIE on BOTTOM "+3V3_PCIE_L04_P103" (solid, remove dead copper, pour order 103): 98.598,53.211 98.598,68.092 90.645,76.045 65.837,76.045 57.826,68.034 57.826,62.439 63.398,62.439 63.398,67.374 65.744,69.721 83.55,69.721 84.567,69.721 85.129,69.159 85.129,64.43 84.473,63.774 80.836,63.774 78.062,63.774 74.456,60.168 74.456,57.516 76.006,57.516 76.986,58.419 87.183,58.419 92.391,53.211
VCC on BOTTOM "VCC_L04_P087" (solid, remove dead copper, pour order 87): 63.248,86.5 63.248,80.752 55.364,72.868 51.964,72.868 42.064,82.768 31.764,82.768 26.964,77.968 23.227,77.968 23.227,86.5
VIN on BOTTOM "VIN_L04_P126" (solid, remove dead copper, pour order 126): 54.805,7.338 55.042,7.574 55.529,7.574 55.94,7.198 55.94,1.219 54.971,0.25 12.893,0.25 12.893,17.8 24.937,27.735 27.142,25.531 14.334,15.087 14.334,3.43 15.899,1.864 49.332,1.864 54.666,7.198
VIN on BOTTOM "r" (solid, remove dead copper, pour order 118): 38.308,23.195 40.951,20.552 40.951,16.513 35.221,16.513 35.221,23.903 35.221,31.035 38.308,31.035
GND on TOP "C" (solid, remove dead copper, pour order 134): 113.978,86.902 113.978,0.402 -0.026,0.402 -0.026,86.902
VIN on TOP "TOP-VIN" (solid, remove dead copper, pour order 105): 32.14,30.04 37.791,30.04 37.916,30.165 37.916,31.28 38.4,31.764 44.953,31.764 46.677,30.04 48.566,28.151 48.566,26.434 51.448,23.552 59.383,23.552 62.697,26.866 71.392,26.866 80.582,36.057 93.009,36.057 94.05,37.097 94.05,38.176 104.441,48.567 112.922,48.567 113.515,49.16 113.515,53.015 107.199,53.045 107.226,55.535 104.441,55.535 98.844,50.098 98.844,48.268 95.155,44.58 66.712,44.58 64.146,35.296 42.084,35.296 23.005,54.375 17.819,54.375 17.819,52.435 20.778,49.477 20.735,45.775 30.9,35.61 30.9,33.75 24.75,27.6 24.75,24.6 25.05,24.3 26.4,24.3
VIN on TOP "VIN_L01_P114" (solid, remove dead copper, pour order 114): 2.148,86.5 12.804,86.5 13.201,86.068 13.201,82.772 13.793,82.18 17.124,82.18 18.979,80.324 18.979,63.951 23.786,59.144 23.786,50.256 12.577,50.256 12.577,78.006 8.827,78.006 4.314,82.518 2.216,82.518 2.148,82.586
VIN on TOP "VIN_L01_P133" (solid, remove dead copper, pour order 133): 79.2,50.311 71.743,50.311 66.697,45.264 66.697,33.707 77,33.707 77,47.5 77.5,48 79.2,48
NetC23_2 on TOP "NETC23_2_L01_P129" (solid, remove dead copper, pour order 129): 15.614,59.318 15.614,51.518 10.58,51.518 10.58,54.15 12.78,54.15 12.78,59.318
NetC23_2 on TOP "NETC23_2_L01_P112" (solid, remove dead copper, pour order 112): 13.045,61.249 15.272,61.249 15.272,52.498 10.564,52.498 10.564,54.868 11.412,55.717 11.464,59.668
LICELL_1 on TOP "LICELL_1_L01_P123" (solid, remove dead copper, pour order 123): 31.68,63.192 30.892,63.98 24.393,63.98 24.081,63.668 24.081,62.877 24.254,62.704 30.916,62.704 31.351,61.939 31.68,61.939
VIN on TOP "VIN_L01_P131" (solid, remove dead copper, pour order 131): 37.5,15.33 38.504,15.33 38.504,16.271 41.6,16.271 41.6,15.292 42.153,15.292 42.153,17.822 37.244,17.822 37.244,15.322
VCC on TOP "VCC_L01_P122" (solid, remove dead copper, pour order 122): 114,57.016 96.048,57.016 96.048,53.208 114,53.208
VCC on TOP "VCC_L01_P130" (solid, remove dead copper, pour order 130): 15.957,26.525 17.562,26.525 20.184,26.525 22.604,24.106 24.406,24.106 24.406,30.294 16.499,30.294 15.957,29.752 15.957,28.752
+3V3_BUCK on TOP "+3V3_BUCK_L01_P127" (solid, remove dead copper, pour order 127): 81.915,54.86 92.065,54.86 93.605,53.32 95.935,53.32 95.935,50.415 92.121,50.415 90.346,48.64 87.675,48.64 87.675,51.367 86.46,52.581 81.915,52.581
GND on SIG "GND_L03_P125" (solid, remove dead copper, pour order 125): 113.843,86.306 113.843,-0.194 -0.161,-0.194 -0.161,86.306
VCC on SIG "SIG-VCC" (solid, remove dead copper, pour order 111): 13.567,37.57 22.448,28.689 24.989,28.689 24.989,30.256 27.231,32.498 27.231,35.625 30.698,39.092 51.298,39.092 54.698,42.492 57.85,42.492 69.369,53.599 78.647,53.599 79.757,52.385 99.127,52.385 99.127,53.599 99.127,55.933 81.457,55.933 80.167,57.224 73.364,57.224 71.843,55.703 67.669,55.703 64.35,52.385 51.885,52.385 44.913,45.413 42.436,45.413 41.92,45.929 41.92,49.094 45.957,53.131 45.957,61.675 42.639,64.992 34.28,64.992 34.28,53.752 26.957,53.752 26.957,77.752 13.567,77.752
VIN on SIG "VIN_L03_P119" (solid, remove dead copper, pour order 119): 8.64,85.824 9.316,86.5 65.997,86.5 65.997,81.273 64.951,80.227 26.773,80.227 25.099,81.901 9.65,81.901 8.65,82.901 8.65,85.801
VCC on SIG "VCC_L03_P121" (solid, remove dead copper, pour order 121): 1.838,75.52 14.301,75.52 22.66,68.551 26.816,68.557 26.954,75.326 26.962,80.071 25.215,81.752 14.85,81.752 12.123,79.28 1.838,79.28
GND on GND "GND_L02_P091" (solid, remove dead copper, pour order 91): 114.004,86.5 114.004,0 0,0 0,86.5

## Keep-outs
TOP:
  circle w1.8: c95,18 r2.2
  circle w1.8: c20,35 r2.2
  circle w1.8: c54.8,78.7 r2.2
  circle w1.8: c20,66 r2.2
BOTTOM:
  circle w1.8: c95,18 r2.2
  circle w1.8: c20,35 r2.2
  circle w1.8: c54.8,78.7 r2.2
  circle w1.8: c20,66 r2.2

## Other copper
TOP:
  text ".Version" at 98.614,15.438 h1.52

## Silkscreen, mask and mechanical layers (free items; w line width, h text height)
Top Designator:
  text "USB" at 40.499,2.312 h1 r180
Route Tool Path:
  lines w2: -1,13 -1,0.5 ; -1,18 -1,68.5 ; -1,73.5 -1,86 ; 115,13 115,0.5 ; 115,18 115,68.5 ; 115,73.5 115,86 ; -1,0.496 ccw(c0.5,0.5) 0.496,-1 ; -1,0.496 cw(c0.5,0.5) -1,0.5 ; -1,0.496 cw(c0,0.5) -1,0.5 ; -1,86 cw(c0.5,86) 0.496,87.5 ; -1,86 -1,86 ; -1,86 -1,86 ; 0.496,-1 ccw(c0.5,0) 0.5,-1 ; 0.496,-1 ccw(c0.5,0.5) 0.5,-1 ; 0.496,87.5 cw(c0.5,86) 0.5,87.5 ; 0.496,87.5 cw(c0.5,86.5) 0.5,87.5 ; 0.5,-1 113.5,-1 ; 0.5,87.5 113.5,87.5 ; 113.5,-1 ccw(c113.5,0.5) 115,0.496 ; 113.5,-1 113.5,-1 ; 113.5,87.5 ccw(c113.5,86.5) 113.5,87.5 ; 113.5,87.5 cw(c113.5,86) 115,86 ; 113.5,87.5 ccw(c113.5,86.5) 113.5,87.5 ; 115,0.496 ccw(c113.5,0.5) 115,0.5 ; 115,0.496 ccw(c114,0.5) 115,0.5 ; 115,86 ccw(c113.5,86) 115,86 ; 115,86 115,86
Board:
  the board outline again, w0.1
